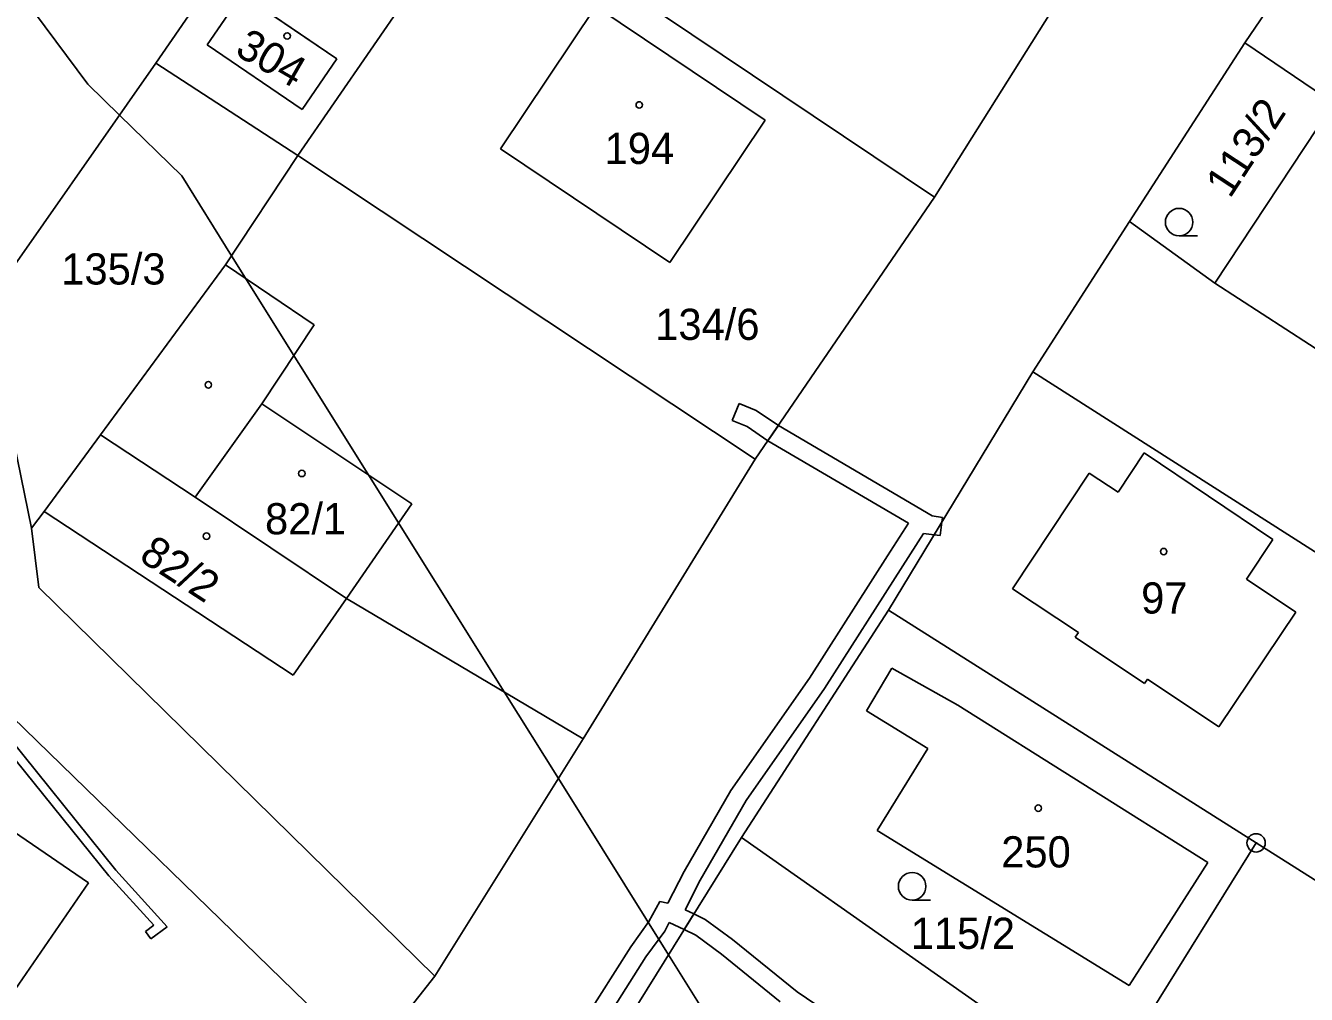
# Model space of a CAD drawing. Extents: x -747333 to -745433, y -1133152 to -1130600.
# Drawn here: x -746336.6 to -746266.8, y -1131795.9 to -1131743.1 of the extents above; entities that cross this region are included whole.
import ezdxf

# ---------------------------------------------------------------- set-up
doc = ezdxf.new("R2010")
doc.units = 0
for name, color, linetype in [('Vrstva 1', 7, 'Continuous'), ('Vrstva 18', 7, 'Continuous'), ('Vrstva 19', 7, 'Continuous'), ('Vrstva 24', 7, 'Continuous'), ('Vrstva 25', 7, 'Continuous'), ('Vrstva 3', 7, 'Continuous'), ('Vrstva 30', 7, 'Continuous'), ('Vrstva 37', 7, 'Continuous'), ('Vrstva 4', 7, 'Continuous'), ('Vrstva 52', 7, 'Continuous')]:
    doc.layers.add(name, color=color, linetype=linetype)

msp = doc.modelspace()

# ---------------------------------------------------------------- linework, layer by layer
at = {"layer": 'Vrstva 1'}
for p, q in [((-746324.84, -1131741.34), (-746326.74, -1131744.1)), ((-746319.67, -1131744.87), (-746324.84, -1131741.34)), ((-746326.74, -1131744.1), (-746321.55, -1131747.63)), ((-746321.55, -1131747.63), (-746319.67, -1131744.87)), ((-746290.77, -1131780.41), (-746289.39, -1131778.09)), ((-746289.39, -1131778.09), (-746285.79, -1131780.1)), ((-746287.43, -1131782.46), (-746290.77, -1131780.41)), ((-746285.79, -1131780.1), (-746272.16, -1131788.68)), ((-746290.19, -1131786.93), (-746287.43, -1131782.46)), ((-746276.46, -1131795.38), (-746290.19, -1131786.93)), ((-746277.93, -1131801.12), (-746269.53, -1131787.61)), ((-746272.16, -1131788.68), (-746276.46, -1131795.38))]:
    msp.add_line(p, q, dxfattribs=at)
for points in [[(-746311.89, -1131735.77), (-746321.79, -1131750.13)], [(-746287.07, -1131752.41), (-746311.89, -1131735.77)], [(-746287.07, -1131752.41), (-746277.08, -1131736.51)], [(-746264.78, -1131736.1), (-746270.15, -1131743.99)], [(-746326.66, -1131740.92), (-746329.53, -1131745.1)], [(-746310.74, -1131749.77), (-746305.53, -1131742.02)], [(-746305.53, -1131742.02), (-746296.31, -1131748.21)], [(-746270.15, -1131743.99), (-746276.43, -1131753.74)], [(-746270.15, -1131743.99), (-746265.3, -1131747.29)], [(-746329.53, -1131745.1), (-746338.81, -1131758.34)], [(-746321.79, -1131750.13), (-746329.53, -1131745.1)], [(-746296.31, -1131748.21), (-746301.51, -1131755.97)], [(-746271.78, -1131757.1), (-746266.18, -1131748.62)], [(-746301.51, -1131755.97), (-746310.74, -1131749.77)], [(-746325.74, -1131756.1), (-746321.79, -1131750.13)], [(-746321.79, -1131750.13), (-746296.84, -1131766.7)], [(-746296.84, -1131766.7), (-746287.07, -1131752.41)], [(-746276.43, -1131753.74), (-746281.7, -1131761.93)], [(-746271.78, -1131757.1), (-746276.43, -1131753.74)], [(-746332.56, -1131765.37), (-746325.74, -1131756.1)], [(-746336.31, -1131770.46), (-746338.81, -1131758.34)], [(-746281.7, -1131761.93), (-746289.58, -1131774.93)], [(-746263.38, -1131773.61), (-746281.7, -1131761.93)], [(-746335.63, -1131769.54), (-746332.56, -1131765.37)], [(-746327.38, -1131768.77), (-746332.56, -1131765.37)], [(-746296.84, -1131766.7), (-746306.23, -1131781.93)], [(-746319.13, -1131774.28), (-746327.38, -1131768.77)], [(-746336.31, -1131770.46), (-746335.63, -1131769.54)], [(-746335.91, -1131773.68), (-746336.31, -1131770.46)], [(-746314.31, -1131794.88), (-746335.91, -1131773.68)], [(-746306.23, -1131781.93), (-746319.13, -1131774.28)], [(-746289.58, -1131774.93), (-746297.6, -1131787.32)], [(-746269.53, -1131787.61), (-746289.58, -1131774.93)], [(-746340.04, -1131778.16), (-746318.01, -1131799.56)], [(-746314.31, -1131794.88), (-746306.23, -1131781.93)], [(-746297.6, -1131787.32), (-746303.67, -1131797.07)], [(-746277.93, -1131801.12), (-746297.6, -1131787.32)], [(-746264.99, -1131790.48), (-746269.53, -1131787.61)], [(-746318.01, -1131799.56), (-746314.31, -1131794.88)]]:
    msp.add_lwpolyline(points, dxfattribs=at)
at = {"layer": 'Vrstva 24'}
msp.add_line((-746269.58, -1131787.61), (-746269.48, -1131787.61), dxfattribs=at)
msp.add_circle((-746269.53, -1131787.61), 0.499289, dxfattribs=at)
at = {"layer": 'Vrstva 25'}
for p, q in [((-746273.73, -1131754.52), (-746272.73, -1131754.52)), ((-746288.29, -1131790.73), (-746287.29, -1131790.73))]:
    msp.add_line(p, q, dxfattribs=at)
for centre, radius in [((-746322.37, -1131743.62), 0.174503), ((-746303.17, -1131747.38), 0.174503), ((-746273.73, -1131753.77), 0.75), ((-746326.67, -1131762.64), 0.174503), ((-746321.57, -1131767.47), 0.174503), ((-746326.77, -1131770.89), 0.174503), ((-746274.57, -1131771.73), 0.174503), ((-746281.41, -1131785.72), 0.174503), ((-746288.29, -1131789.98), 0.75)]:
    msp.add_circle(centre, radius, dxfattribs=at)
at = {"layer": 'Vrstva 3'}
for points in [[(-746324.84, -1131741.34), (-746326.74, -1131744.1)], [(-746319.67, -1131744.87), (-746324.84, -1131741.34)], [(-746310.74, -1131749.77), (-746305.53, -1131742.02)], [(-746305.53, -1131742.02), (-746296.31, -1131748.21)], [(-746326.74, -1131744.1), (-746321.55, -1131747.63)], [(-746321.55, -1131747.63), (-746319.67, -1131744.87)], [(-746296.31, -1131748.21), (-746301.51, -1131755.97)], [(-746271.78, -1131757.1), (-746266.18, -1131748.62)], [(-746301.51, -1131755.97), (-746310.74, -1131749.77)], [(-746262.74, -1131762.94), (-746271.78, -1131757.1)], [(-746323.76, -1131763.68), (-746327.38, -1131768.77)], [(-746315.57, -1131769.12), (-746323.76, -1131763.68)], [(-746335.63, -1131769.54), (-746332.56, -1131765.37)], [(-746327.38, -1131768.77), (-746332.56, -1131765.37)], [(-746277.06, -1131768.5), (-746275.64, -1131766.35)], [(-746275.64, -1131766.35), (-746268.61, -1131771.08)], [(-746282.81, -1131773.77), (-746278.63, -1131767.46)], [(-746278.63, -1131767.46), (-746277.06, -1131768.5)], [(-746319.13, -1131774.28), (-746327.38, -1131768.77)], [(-746319.13, -1131774.28), (-746327.38, -1131768.77)], [(-746322.04, -1131778.47), (-746335.63, -1131769.54)], [(-746319.13, -1131774.28), (-746315.57, -1131769.12)], [(-746268.61, -1131771.08), (-746270.05, -1131773.23)], [(-746279.22, -1131776.15), (-746282.81, -1131773.77)], [(-746270.05, -1131773.23), (-746267.36, -1131775.04)], [(-746319.13, -1131774.28), (-746322.04, -1131778.47)], [(-746267.36, -1131775.04), (-746271.57, -1131781.29)], [(-746279.39, -1131776.39), (-746279.22, -1131776.15)], [(-746275.62, -1131778.92), (-746279.39, -1131776.39)], [(-746290.77, -1131780.41), (-746289.39, -1131778.09)], [(-746289.39, -1131778.09), (-746285.79, -1131780.1)], [(-746275.46, -1131778.68), (-746275.62, -1131778.92)], [(-746271.57, -1131781.29), (-746275.46, -1131778.68)], [(-746287.43, -1131782.46), (-746290.77, -1131780.41)], [(-746285.79, -1131780.1), (-746272.16, -1131788.68)], [(-746290.19, -1131786.93), (-746287.43, -1131782.46)], [(-746333.21, -1131789.79), (-746340.23, -1131799.97), (-746348.05, -1131794.58), (-746341.05, -1131784.42), (-746333.21, -1131789.79)], [(-746276.46, -1131795.38), (-746290.19, -1131786.93)], [(-746272.16, -1131788.68), (-746276.46, -1131795.38)]]:
    msp.add_lwpolyline(points, dxfattribs=at)
at = {"layer": 'Vrstva 30'}
for p, q in [((-746338.64, -1131780.51), (-746331.72, -1131789.09)), ((-746332.1, -1131789.41), (-746339.06, -1131780.79)), ((-746331.72, -1131789.09), (-746328.91, -1131792.18)), ((-746329.65, -1131792.1), (-746332.1, -1131789.41)), ((-746330.1, -1131792.44), (-746329.65, -1131792.1)), ((-746329.8, -1131792.84), (-746330.1, -1131792.44)), ((-746328.91, -1131792.18), (-746329.8, -1131792.84))]:
    msp.add_line(p, q, dxfattribs=at)
for points in [[(-746298.1, -1131764.58), (-746297.72, -1131763.66)], [(-746297.72, -1131763.66), (-746296.8, -1131764.04)], [(-746297.28, -1131764.92), (-746298.1, -1131764.58)], [(-746296.8, -1131764.04), (-746295.58, -1131764.86)], [(-746296.15, -1131765.69), (-746297.28, -1131764.92)], [(-746296.15, -1131765.69), (-746295.58, -1131764.86)], [(-746295.58, -1131764.86), (-746296.15, -1131765.69)], [(-746295.58, -1131764.86), (-746287.19, -1131769.79)], [(-746288.49, -1131770.19), (-746296.15, -1131765.69)], [(-746289.64, -1131771.96), (-746288.49, -1131770.19)], [(-746287.19, -1131769.79), (-746286.64, -1131769.87)], [(-746286.67, -1131770.13), (-746287.09, -1131770.82)], [(-746287.09, -1131770.82), (-746286.67, -1131770.13)], [(-746286.67, -1131770.13), (-746286.76, -1131770.86)], [(-746286.64, -1131769.87), (-746286.67, -1131770.13)], [(-746287.66, -1131770.75), (-746288.8, -1131772.5)], [(-746287.09, -1131770.82), (-746287.66, -1131770.75)], [(-746286.76, -1131770.86), (-746287.09, -1131770.82)], [(-746293.89, -1131778.63), (-746289.64, -1131771.96)], [(-746288.8, -1131772.5), (-746293.06, -1131779.19)], [(-746298.18, -1131784.76), (-746293.89, -1131778.63)], [(-746293.06, -1131779.19), (-746297.34, -1131785.3)], [(-746300.72, -1131789.17), (-746298.18, -1131784.76)], [(-746297.34, -1131785.3), (-746299.84, -1131789.65)], [(-746301.62, -1131790.9), (-746300.72, -1131789.17)], [(-746299.84, -1131789.65), (-746300.67, -1131791.26)], [(-746302.64, -1131791.9), (-746302.05, -1131790.8)], [(-746302.05, -1131790.8), (-746301.62, -1131790.9)], [(-746303.63, -1131793.27), (-746302.64, -1131791.9)], [(-746300.72, -1131792.34), (-746300.19, -1131791.48)], [(-746300.19, -1131791.48), (-746300.72, -1131792.34)], [(-746300.67, -1131791.26), (-746300.19, -1131791.48)], [(-746300.19, -1131791.48), (-746299.57, -1131791.78)], [(-746299.57, -1131791.78), (-746298.08, -1131792.87)], [(-746301.78, -1131792.42), (-746302.81, -1131793.83)], [(-746301.53, -1131791.95), (-746301.78, -1131792.42)], [(-746300.72, -1131792.34), (-746301.53, -1131791.95)], [(-746300.09, -1131792.64), (-746300.72, -1131792.34)], [(-746307.05, -1131798.65), (-746303.63, -1131793.27)], [(-746298.69, -1131793.67), (-746300.09, -1131792.64)], [(-746298.08, -1131792.87), (-746294.55, -1131795.74)], [(-746302.81, -1131793.83), (-746306.21, -1131799.21)], [(-746295.49, -1131796.27), (-746298.69, -1131793.67)], [(-746294.55, -1131795.74), (-746291.1, -1131798.07)]]:
    msp.add_lwpolyline(points, dxfattribs=at)
at = {"layer": 'Vrstva 37'}
for centre in [(-746322.37, -1131743.62), (-746303.17, -1131747.38), (-746321.57, -1131767.47), (-746326.77, -1131770.89), (-746274.57, -1131771.73), (-746281.41, -1131785.72)]:
    msp.add_circle(centre, 0.174503, dxfattribs=at)
at = {"layer": 'Vrstva 4'}
for points in [[(-746325.74, -1131756.1), (-746320.9, -1131759.36)], [(-746262.74, -1131762.94), (-746271.78, -1131757.1)], [(-746320.9, -1131759.36), (-746323.76, -1131763.68)], [(-746323.76, -1131763.68), (-746327.38, -1131768.77)], [(-746315.57, -1131769.12), (-746323.76, -1131763.68)], [(-746277.06, -1131768.5), (-746275.64, -1131766.35)], [(-746275.64, -1131766.35), (-746268.61, -1131771.08)], [(-746282.81, -1131773.77), (-746278.63, -1131767.46)], [(-746278.63, -1131767.46), (-746277.06, -1131768.5)], [(-746322.04, -1131778.47), (-746335.63, -1131769.54)], [(-746319.13, -1131774.28), (-746315.57, -1131769.12)], [(-746268.61, -1131771.08), (-746270.05, -1131773.23)], [(-746279.22, -1131776.15), (-746282.81, -1131773.77)], [(-746270.05, -1131773.23), (-746267.36, -1131775.04)], [(-746319.13, -1131774.28), (-746322.04, -1131778.47)], [(-746267.36, -1131775.04), (-746271.57, -1131781.29)], [(-746279.39, -1131776.39), (-746279.22, -1131776.15)], [(-746275.62, -1131778.92), (-746279.39, -1131776.39)], [(-746275.46, -1131778.68), (-746275.62, -1131778.92)], [(-746271.57, -1131781.29), (-746275.46, -1131778.68)], [(-746333.21, -1131789.79), (-746340.23, -1131799.97), (-746348.05, -1131794.58), (-746341.05, -1131784.42), (-746333.21, -1131789.79)]]:
    msp.add_lwpolyline(points, dxfattribs=at)
at = {"layer": 'Vrstva 52'}
msp.add_lwpolyline([(-746298.31, -1131829.62), (-746296.86, -1131819.7), (-746296.69, -1131818.5), (-746296.69, -1131813.19), (-746296.69, -1131808.25), (-746297.44, -1131805.15), (-746297.94, -1131803.13), (-746298.81, -1131798.12), (-746299.85, -1131796.47), (-746301.58, -1131793.71), (-746307.58, -1131784.1), (-746310.54, -1131779.38), (-746325.41, -1131755.6), (-746328.12, -1131751.25), (-746331.52, -1131747.94), (-746333.25, -1131746.25), (-746340.87, -1131736)], dxfattribs=at)

# ---------------------------------------------------------------- texts
at = {"layer": 'Vrstva 18'}
msp.add_text('113/2', height=1.7, rotation=56.76831, dxfattribs=at).set_placement((-746270.96, -1131752.53))
for s, p in [('135/3', (-746334.69, -1131757.17)), ('134/6', (-746302.3, -1131760.19)), ('115/2', (-746288.36736, -1131793.39))]:
    msp.add_text(s, height=1.7, dxfattribs=at).set_placement(p)
at = {"layer": 'Vrstva 19'}
for s, rotation, p in [('304', 330.05124, (-746325.291238, -1131744.603195)), ('82/2', 327.01149, (-746330.52, -1131772.17))]:
    msp.add_text(s, height=1.7, rotation=rotation, dxfattribs=at).set_placement(p)
for s, p in [('194', (-746305.06, -1131750.6)), ('82/1', (-746323.58, -1131770.79)), ('97', (-746275.8, -1131775.11)), ('250', (-746283.43, -1131788.95))]:
    msp.add_text(s, height=1.7, dxfattribs=at).set_placement(p)

doc.saveas('drawing.dxf')
